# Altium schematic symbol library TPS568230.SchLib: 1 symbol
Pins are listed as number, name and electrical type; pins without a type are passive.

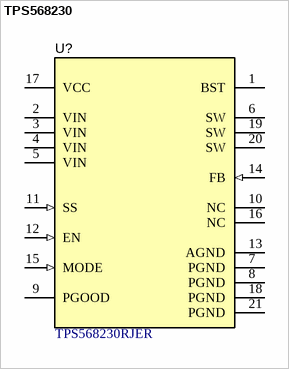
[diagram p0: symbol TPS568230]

## TPS568230
designator U?, comment TPS568230RJER
4.5V to 18 V Input, 8-A Synchronous Step-Down Voltage Regulator, RJE0020A (VQFN-HR-20); Alternate PartNumber: TPS568230RJET; Alternate Manufacturer: Texas Instruments; CompType: IC; AEC Qualified: N; AEC Category: Q200; SizeY_mm: 3; SizeAreaWB_mm2: 16; SizeZ_mm: 1; SizeArea_mm2: 9
footprint RJE0020A (QFN, 20-Leads, Body 3x3mm, Pitch 0.45mm, Thermal Pad 0.76x0.68mm)
pins: 1 BST (power), 2 VIN (power), 3 VIN (power), 4 VIN (power), 5 VIN (power), 6 SW (power), 7 PGND (power), 8 PGND (power), 9 PGOOD (oc), 10 NC, 11 SS (in), 12 EN (in), 13 AGND (power), 14 FB (in), 15 MODE (in), 16 NC, 17 VCC (power), 18 PGND (power), 19 SW (power), 20 SW (power), 21 PGND (power)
